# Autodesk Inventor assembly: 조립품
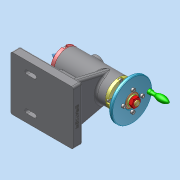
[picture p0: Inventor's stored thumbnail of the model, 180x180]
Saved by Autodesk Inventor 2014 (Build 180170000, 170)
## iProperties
Created: 2026-09
Part Number: 조립품
Document SubType Name: Assembly
Designer: dg
Author: dg
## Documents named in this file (18)
- C:\Users\dg\Desktop\760903V1011\조립품.iam
- C:\Users\dg\Desktop\760903V1011\본체.ipt
- C:\Users\dg\Desktop\760903V1011\가져온 구성요소\나사축\나사축.ipt
- C:\Users\dg\Desktop\760903V1011\가져온 구성요소\돌림판\돌림판.ipt
- C:\Users\dg\Desktop\760903V1011\가져온 구성요소\부시\부시.ipt
- C:\Users\dg\Desktop\760903V1011\가져온 구성요소\평행 키 4x4x10\평행 키 4x4x10.ipt
- C:\Users\dg\Desktop\760903V1011\가져온 구성요소\플랜지\플랜지.ipt
- C:\Users\dg\Desktop\760903V1011\가져온 구성요소\6각 너트 M8\6각 너트 M8.ipt
- C:\Users\dg\Desktop\760903V1011\가져온 구성요소\평 와셔 M8\평 와셔 M8.ipt
- C:\Users\dg\Desktop\760903V1011\가져온 구성요소\핸들\핸들.ipt
- C:\Users\dg\Desktop\760903V1011\가져온 구성요소\6각 구멍붙이 볼트 M3x8\6각 구멍붙이 볼트 M3x8.ipt
- C:\Users\dg\Desktop\760903V1011\가져온 구성요소\커버\커버.ipt
- C:\Users\dg\Desktop\760903V1011\가져온 구성요소\스톱퍼\스톱퍼.ipt
- C:\Users\dg\Desktop\760903V1011\가져온 구성요소\가이드 부시\가이드 부시.ipt
- C:\Users\dg\Desktop\760903V1011\가져온 구성요소\멈춤나사 M3\멈춤나사 M3.ipt
- C:\Users\dg\Desktop\760903V1011\가져온 구성요소\센터\센터.ipt
- C:\Users\dg\Desktop\760903V1011\가져온 구성요소\센터홀더\센터홀더.ipt
- C:\Users\dg\Desktop\760903V1011\가져온 구성요소\슬리브\슬리브.ipt
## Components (16 placed, 5 different names)
1. 플랜지:1
2. 6각 너트 M8:1
3. 핸들:1
4. 가이드 부시:1 — 플러쉬:1
5. 6각 구멍붙이 볼트 M3x8:1
6. 6각 구멍붙이 볼트 M3x8:2
7. 6각 구멍붙이 볼트 M3x8:3
8. 6각 구멍붙이 볼트 M3x8:4
9. 6각 구멍붙이 볼트 M3x8:5
10. 6각 구멍붙이 볼트 M3x8:6
11. 6각 구멍붙이 볼트 M3x8:7
12. 6각 구멍붙이 볼트 M3x8:8
13. 6각 구멍붙이 볼트 M3x8:9
14. 6각 구멍붙이 볼트 M3x8:10
15. 6각 구멍붙이 볼트 M3x8:11
16. 6각 구멍붙이 볼트 M3x8:12
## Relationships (1: Flush 1)
- 플러쉬:1 [Flush]: 가이드 부시:1
